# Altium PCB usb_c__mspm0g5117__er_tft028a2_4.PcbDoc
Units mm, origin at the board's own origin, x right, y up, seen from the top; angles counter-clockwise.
Board outline 82 x 52 mm, 2 copper layers (Top, Bottom), stack 0 mm thick; 33 components, 30 nets, 218 pads, 119 vias.
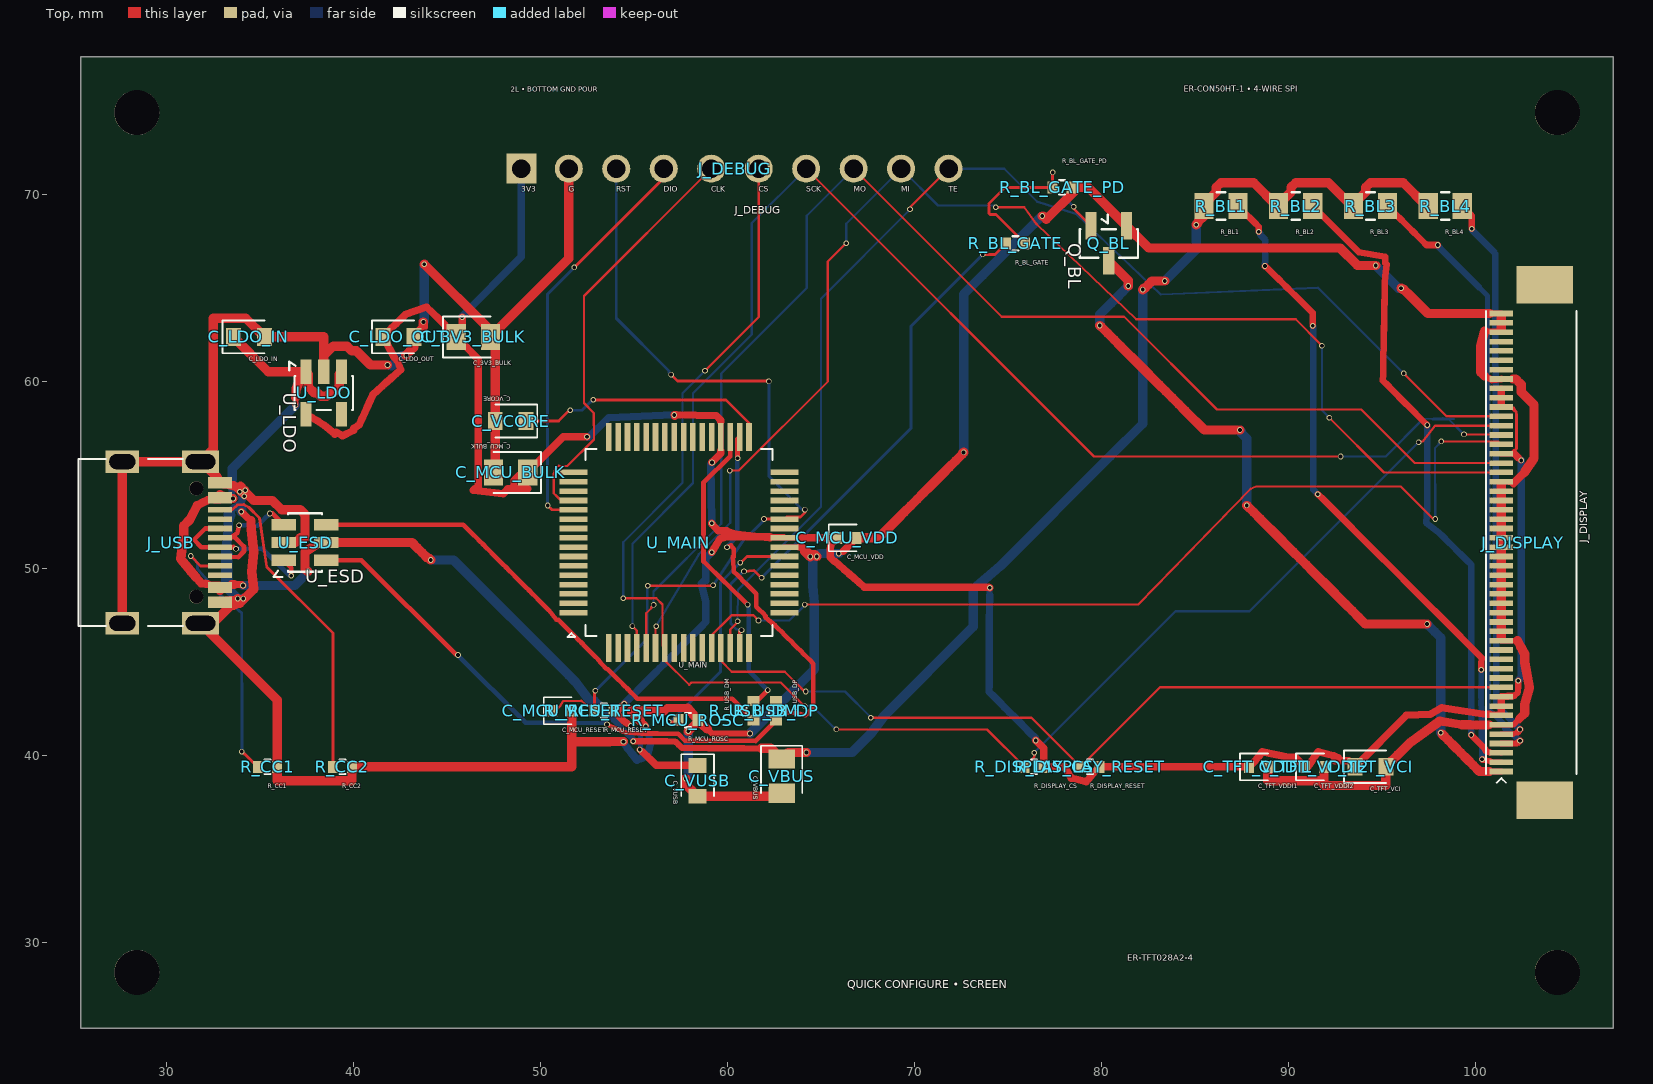
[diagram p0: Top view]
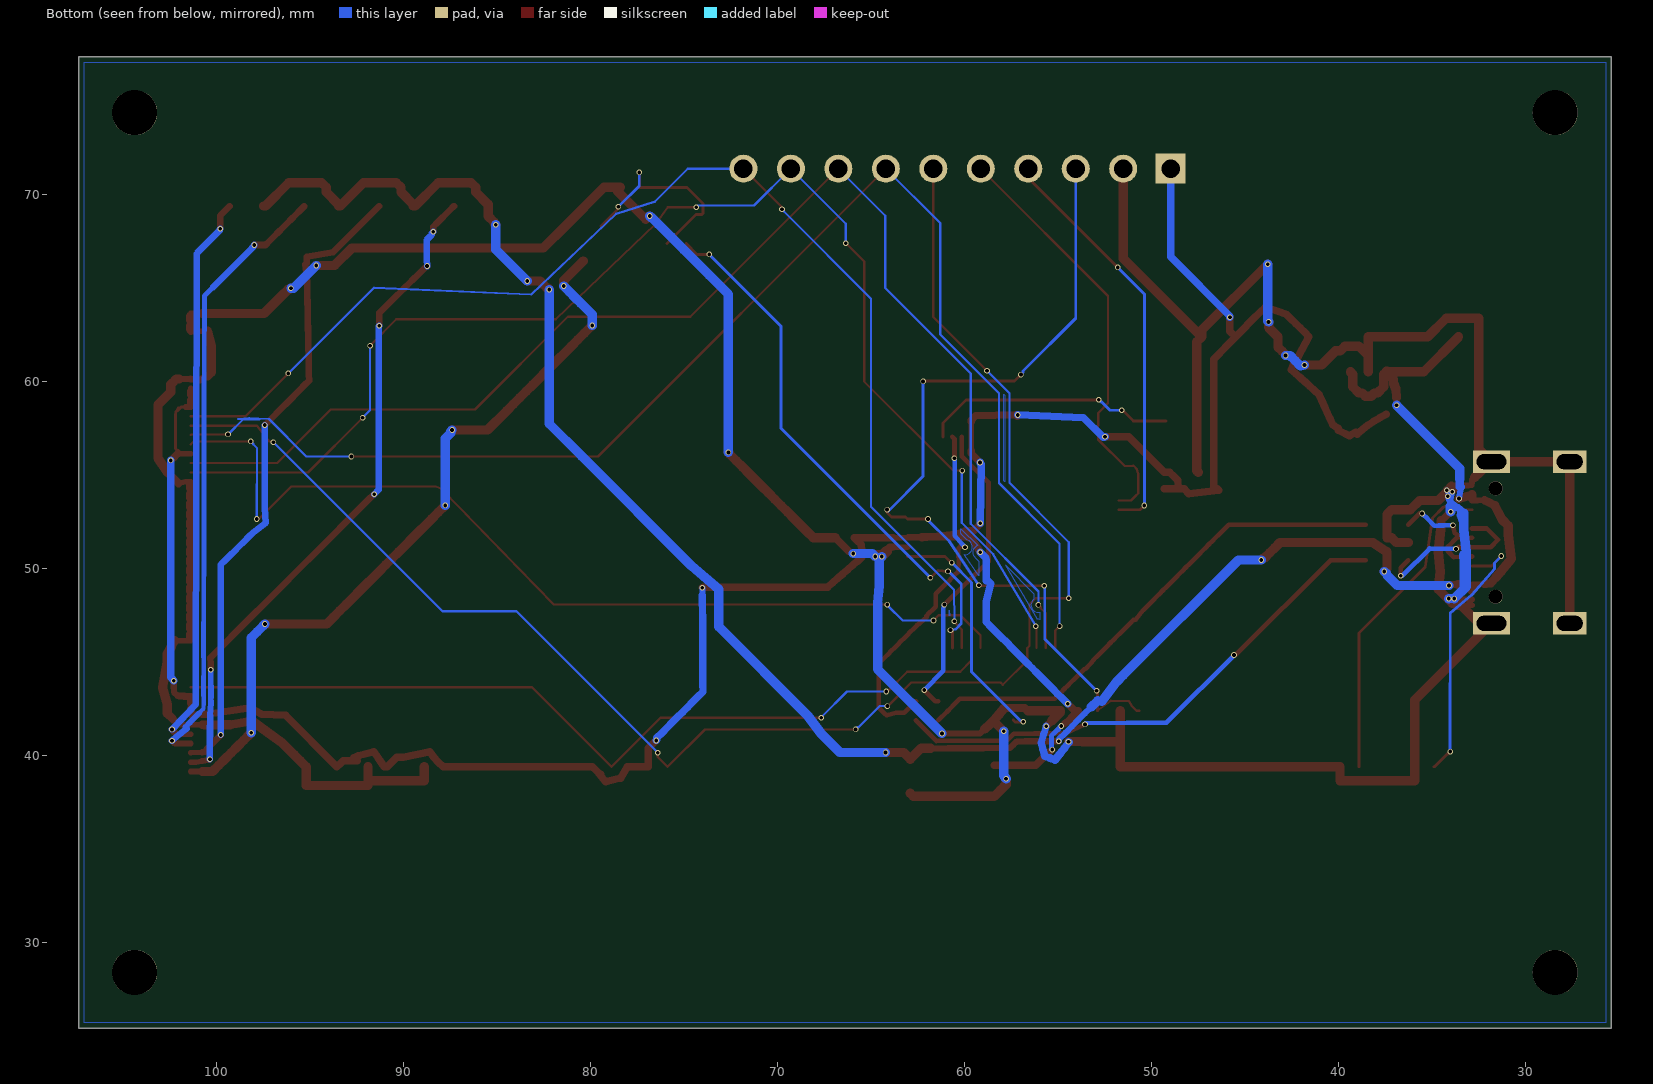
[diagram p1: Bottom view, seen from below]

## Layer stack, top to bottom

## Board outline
25.4,77.4 107.4,77.4 107.4,25.4 25.4,25.4

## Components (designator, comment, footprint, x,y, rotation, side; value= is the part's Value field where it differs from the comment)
C_3V3_BULK "" TSCIRCUIT-2.8500x1.4000mm 46.4,62.4 r0 top
C_LDO_IN "" TSCIRCUIT-2.4500x0.9500mm 34.4,62.4 r0 top
C_LDO_OUT "" TSCIRCUIT-2.4500x0.9500mm 42.4,62.4 r0 top
C_MCU_BULK "" TSCIRCUIT-2.8500x1.4000mm 48.4,55.15 r180 top
C_MCU_RESET "" TSCIRCUIT-1.5600x0.6400mm 51.15,42.4 r0 top
C_MCU_VDD "" TSCIRCUIT-1.5600x0.6400mm 66.4,51.65 r0 top
C_TFT_VCI "" TSCIRCUIT-2.4500x0.9500mm 94.4,39.4 r0 top
C_TFT_VDDI1 "" TSCIRCUIT-1.5600x0.6400mm 88.4,39.4 r0 top
C_TFT_VDDI2 "" TSCIRCUIT-1.5600x0.6400mm 91.4,39.4 r0 top
C_VBUS "" TSCIRCUIT-1.4000x2.8500mm 62.9,38.9 r270 top
C_VCORE "" TSCIRCUIT-2.4500x0.9500mm 48.4,57.9 r180 top
C_VUSB "" TSCIRCUIT-0.9500x2.4500mm 58.4,38.65 r270 top
J_DEBUG "" TSCIRCUIT-24.3600x1.5000mm 60.4,71.4 r0 top
J_DISPLAY "" TSCIRCUIT-4.4500x29.5800mm 103,51.4 r90 top
J_USB "" TSCIRCUIT-6.7732x9.8502mm 30.113,51.4 r90 top
Q_BL "" TSCIRCUIT-2.5000x3.3500mm 80.4,67.4 r270 top
R_BL1 "" TSCIRCUIT-2.8500x1.4000mm 86.4,69.4 r0 top
R_BL2 "" TSCIRCUIT-2.8500x1.4000mm 90.4,69.4 r0 top
R_BL3 "" TSCIRCUIT-2.8500x1.4000mm 94.4,69.4 r0 top
R_BL4 "" TSCIRCUIT-2.8500x1.4000mm 98.4,69.4 r0 top
R_BL_GATE "" TSCIRCUIT-1.5600x0.6400mm 75.4,67.4 r0 top
R_BL_GATE_PD "" TSCIRCUIT-1.5600x0.6400mm 77.9,70.4 r0 top
R_CC1 "" TSCIRCUIT-1.5600x0.6400mm 35.4,39.4 r0 top
R_CC2 "" TSCIRCUIT-1.5600x0.6400mm 39.4,39.4 r0 top
R_DISPLAY_CS "" TSCIRCUIT-1.5600x0.6400mm 76.4,39.4 r0 top
R_DISPLAY_RESET "" TSCIRCUIT-1.5600x0.6400mm 79.4,39.4 r0 top
R_MCU_RESET "" TSCIRCUIT-1.5600x0.6400mm 53.4,42.4 r0 top
R_MCU_ROSC "" TSCIRCUIT-1.5600x0.6400mm 57.9,41.9 r0 top
R_USB_DM "" TSCIRCUIT-0.6400x1.5600mm 61.4,42.4 r90 top
R_USB_DP "" TSCIRCUIT-0.6400x1.5600mm 62.6,42.4 r90 top
U_ESD "" TSCIRCUIT-3.6000x2.5000mm 37.4,51.4 r0 top
U_LDO "" TSCIRCUIT-2.5000x3.6000mm 38.4,59.4 r270 top
U_MAIN "" TSCIRCUIT-12.8000x12.8000mm 57.4,51.4 r0 top

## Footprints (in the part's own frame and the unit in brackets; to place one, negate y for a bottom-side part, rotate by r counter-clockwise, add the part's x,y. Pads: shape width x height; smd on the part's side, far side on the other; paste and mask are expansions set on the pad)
TSCIRCUIT-0.6400x1.5600mm [mm]
  rect 0.54x0.64 smd: 1(-0.51,0) 2(0.51,0)
  silkscreen extent -0.15,-0.38 0.15,0.38
TSCIRCUIT-0.9500x2.4500mm [mm]
  rect 0.8x0.95 smd: 1(-0.825,0) 2(0.825,0)
  silkscreen extent -1.43,-0.87 0.82,0.87
TSCIRCUIT-1.4000x2.8500mm [mm]
  rect 1.025x1.4 smd: 1(-0.913,0) 2(0.913,0)
  silkscreen extent -1.62,-1.1 0.91,1.1
TSCIRCUIT-1.5600x0.6400mm [mm]
  rect 0.54x0.64 smd: 1(-0.51,0) 2(0.51,0)
  silkscreen extent -0.98,-0.72 0.51,0.72
TSCIRCUIT-2.4500x0.9500mm [mm]
  rect 0.8x0.95 smd: 1(-0.825,0) 2(0.825,0)
  silkscreen extent -1.43,-0.87 0.82,0.87
TSCIRCUIT-2.5000x3.3500mm [mm]
  rect 1.475x0.6 smd: 1(-0.938,-0.95) 2(-0.938,0.95) 3(0.937,0)
  silkscreen extent -1.54,-1.56 0.76,1.56
TSCIRCUIT-2.5000x3.6000mm [mm]
  rect 1.325x0.6 smd: 1(-1.137,-0.95) 2(-1.137,0) 3(-1.137,0.95) 4(1.138,0.95) 5(1.138,-0.95)
  silkscreen extent -1.69,-1.84 0.91,1.56
TSCIRCUIT-2.8500x1.4000mm [mm]
  rect 1.025x1.4 smd: 1(-0.913,0) 2(0.913,0)
  silkscreen extent -1.63,-1.1 0.91,1.1
TSCIRCUIT-3.6000x2.5000mm [mm]
  rect 1.325x0.6 smd: 1(-1.137,-0.95) 2(-1.137,0) 3(-1.137,0.95) 4(1.138,0.95) 5(1.138,0) 6(1.138,-0.95)
  silkscreen extent -1.69,-1.84 0.91,1.56
TSCIRCUIT-4.4500x29.5800mm [mm]
  rect 0.3x1.25 smd: 1(-12.25,1.6) 2(-11.75,1.6) 3(-11.25,1.6) 4(-10.75,1.6) 5(-10.25,1.6) 6(-9.75,1.6) 7(-9.25,1.6) 8(-8.75,1.6) 9(-8.25,1.6) 10(-7.75,1.6) 11(-7.25,1.6) 12(-6.75,1.6) 13(-6.25,1.6) 14(-5.75,1.6) 15(-5.25,1.6) 16(-4.75,1.6) 17(-4.25,1.6) 18(-3.75,1.6) 19(-3.25,1.6) 20(-2.75,1.6) 21(-2.25,1.6) 22(-1.75,1.6) 23(-1.25,1.6) 24(-0.75,1.6) 25(-0.25,1.6) 26(0.25,1.6) 27(0.75,1.6) 28(1.25,1.6) 29(1.75,1.6) 30(2.25,1.6) 31(2.75,1.6) 32(3.25,1.6) 33(3.75,1.6) 34(4.25,1.6) 35(4.75,1.6) 36(5.25,1.6) 37(5.75,1.6) 38(6.25,1.6) 39(6.75,1.6) 40(7.25,1.6) 41(7.75,1.6) 42(8.25,1.6) 43(8.75,1.6) 44(9.25,1.6) 45(9.75,1.6) 46(10.25,1.6) 47(10.75,1.6) 48(11.25,1.6) 49(11.75,1.6) 50(12.25,1.6)
  rect 2x3 smd: 51(13.79,-0.725) 52(-13.79,-0.725)
  silkscreen extent -12.85,-2.43 12.4,2.42
TSCIRCUIT-6.7732x9.8502mm [mm]
  rect 0.3x1.3 smd: 1(-3.35,-2.737) 2(-3.05,-2.737) 3(-2.55,-2.737) 4(-2.25,-2.737) 5(-1.75,-2.737) 6(-1.25,-2.737) 7(-0.75,-2.737) 8(-0.25,-2.737) 9(0.25,-2.737) 10(0.75,-2.737) 11(1.25,-2.737) 12(1.75,-2.737) 13(2.55,-2.737) 14(2.25,-2.737) 15(3.35,-2.737) 16(3.05,-2.737)
  rect 1.2x2 hole 0.8 slot 1.6 at 90 deg: 17(-4.325,-1.693) 18(4.325,-1.693)
  rect 1.2x1.8 hole 0.8 slot 1.4 at 90 deg: 19(4.325,2.487) 20(-4.325,2.487)
  round 0.75 hole 0.75 unplated: NPTH-1(-2.9,-1.468) NPTH-2(2.9,-1.468)
  silkscreen extent -4.47,-0.75 4.47,4.83
TSCIRCUIT-12.8000x12.8000mm [mm]
  rect 1.5x0.3 smd: 1(-5.65,-3.75) 2(-5.65,-3.25) 3(-5.65,-2.75) 4(-5.65,-2.25) 5(-5.65,-1.75) 6(-5.65,-1.25) 7(-5.65,-0.75) 8(-5.65,-0.25) 9(-5.65,0.25) 10(-5.65,0.75) 11(-5.65,1.25) 12(-5.65,1.75) 13(-5.65,2.25) 14(-5.65,2.75) 15(-5.65,3.25) 16(-5.65,3.75) 33(5.65,3.75) 34(5.65,3.25) 35(5.65,2.75) 36(5.65,2.25) 37(5.65,1.75) 38(5.65,1.25) 39(5.65,0.75) 40(5.65,0.25) 41(5.65,-0.25) 42(5.65,-0.75) 43(5.65,-1.25) 44(5.65,-1.75) 45(5.65,-2.25) 46(5.65,-2.75) 47(5.65,-3.25) 48(5.65,-3.75)
  rect 0.3x1.5 smd: 17(-3.75,5.65) 18(-3.25,5.65) 19(-2.75,5.65) 20(-2.25,5.65) 21(-1.75,5.65) 22(-1.25,5.65) 23(-0.75,5.65) 24(-0.25,5.65) 25(0.25,5.65) 26(0.75,5.65) 27(1.25,5.65) 28(1.75,5.65) 29(2.25,5.65) 30(2.75,5.65) 31(3.25,5.65) 32(3.75,5.65) 49(3.75,-5.65) 50(3.25,-5.65) 51(2.75,-5.65) 52(2.25,-5.65) 53(1.75,-5.65) 54(1.25,-5.65) 55(0.75,-5.65) 56(0.25,-5.65) 57(-0.25,-5.65) 58(-0.75,-5.65) 59(-1.25,-5.65) 60(-1.75,-5.65) 61(-2.25,-5.65) 62(-2.75,-5.65) 63(-3.25,-5.65) 64(-3.75,-5.65)
  silkscreen extent -5.95,-5.05 5,5
TSCIRCUIT-24.3600x1.5000mm [mm]
  rect 1.6x1.6 hole 1: 1(-11.43,0)
  round 1.5 hole 1: 2(-8.89,0) 3(-6.35,0) 4(-3.81,0) 5(-1.27,0) 6(1.27,0) 7(3.81,0) 8(6.35,0) 9(8.89,0) 10(11.43,0)

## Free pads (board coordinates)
  round 2.4 hole 2.4 unplated: NPTH-3(28.4,28.4) NPTH-4(104.4,28.4) NPTH-5(28.4,74.4) NPTH-6(104.4,74.4)

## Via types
v1: diameter 0.3, hole 0.2, Top to Bottom, 119 vias

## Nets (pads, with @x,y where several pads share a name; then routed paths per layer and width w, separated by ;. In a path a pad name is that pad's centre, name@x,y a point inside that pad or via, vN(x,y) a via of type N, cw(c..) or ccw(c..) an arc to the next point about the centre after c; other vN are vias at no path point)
".J_DEBUG > .pin4 to .U_MAIN > .pin12": J_DEBUG.4 U_MAIN.12 | length 22.1
  Top w0.15: v1(50.378,53.378) 50.606,53.15 U_MAIN.12 ; v1(51.802,66.116) 51.815,66.129 56.59,70.904 J_DEBUG.4
  Bottom w0.15: v1(50.378,53.378) 50.37,53.386 50.37,53.404 50.37,64.684 v1(51.802,66.116)
".J_DEBUG > .pin5 to .U_MAIN > .pin13": J_DEBUG.5 U_MAIN.13 | length 22.8
  Top w0.12: U_MAIN.13 51.093,53.65 50.851,53.892 50.711,54.032 50.711,55.079 50.789,55.33 50.971,55.526 50.993,55.491 51.433,55.49 52.859,56.905 52.852,58.334 52.322,58.863 52.322,64.592 J_DEBUG.5
".U_MAIN > .pin42 to .R_MCU_ROSC > .pin1": R_MCU_ROSC.1 U_MAIN.42 | length 13.3
  Top w0.15: v1(56.86,41.804) 57.294,41.804 R_MCU_ROSC.1 ; v1(60.681,50.326) 60.673,50.3 60.695,50.3 61.046,50.65 U_MAIN.42
  Bottom w0.15: v1(56.86,41.804) 56.921,41.865 57.008,41.865 59.632,44.489 59.632,49.259 v1(60.681,50.326)
BACKLIGHT_ANODE_1: J_DISPLAY.2 R_BL1.2 | length 36.1
  Top w0.3: J_DISPLAY.2@100.785,39.709 101.122,39.65 J_DISPLAY.2
  Top w0.312: v1@100.449,39.767 J_DISPLAY.2@100.785,39.709
  Top w0.35: R_BL1.2 87.534,69.179 87.755,68.957 87.977,68.736 88.199,68.514 88.42,68.293 v1(88.42,68.021) ; v1(88.751,66.191) 88.784,66.181 89.014,65.953 89.245,65.726 89.475,65.499 89.705,65.271 89.935,65.044 90.165,64.816 90.396,64.589 90.626,64.362 90.856,64.134 91.086,63.907 91.316,63.679 91.317,63.339 v1(91.318,62.998) ; v1(91.583,53.984) 91.625,53.942 91.637,53.942 91.879,53.7 92.121,53.459 92.363,53.217 92.605,52.975 92.846,52.733 93.088,52.491 93.33,52.249 93.572,52.007 93.814,51.766 94.056,51.524 94.298,51.282 94.539,51.04 94.781,50.798 95.023,50.556 95.265,50.314 95.507,50.073 95.749,49.831 95.991,49.589 96.232,49.347 96.474,49.105 96.716,48.863 96.958,48.621 97.2,48.38 97.442,48.138 97.684,47.896 97.925,47.654 98.167,47.412 98.409,47.17 98.651,46.928 98.893,46.687 99.135,46.445 99.377,46.203 99.618,45.961 99.86,45.719 100.102,45.477 100.344,45.235 100.335,44.915 v1(100.325,44.594) ; v1(100.371,39.8) 100.433,39.767 v1@100.449,39.767
  Bottom w0.306: 100.319,43.12 100.317,42.825 100.34,42.484 100.363,42.143 ; 100.321,43.709 100.323,44.004 100.324,44.299 v1(100.325,44.594)
  Bottom w0.312: 100.319,43.12 100.32,43.415 100.321,43.709
  Bottom w0.35: v1(88.42,68.021) 88.508,67.933 88.508,67.853 88.644,67.718 88.779,67.582 88.772,67.234 88.765,66.886 88.758,66.539 v1(88.751,66.191) ; v1(91.318,62.998) 91.349,62.967 91.349,62.883 91.349,62.537 91.349,62.19 91.349,61.843 91.349,61.497 91.349,61.15 91.349,60.804 91.349,60.457 91.349,60.11 91.349,59.764 91.349,59.417 91.349,59.071 91.349,58.724 91.349,58.377 91.349,58.031 91.349,57.684 91.349,57.338 91.349,56.991 91.349,56.644 91.349,56.298 91.349,55.951 91.349,55.604 91.349,55.258 91.349,54.911 91.349,54.565 91.349,54.218 v1(91.583,53.984) ; 100.363,42.143 100.364,41.809 100.365,41.474 100.367,41.139 100.368,40.804 100.369,40.469 100.37,40.135 v1(100.371,39.8)
BACKLIGHT_ANODE_2: J_DISPLAY.3 R_BL2.2 | length 34.6
  Top w0.3: 100.775,40.19 J_DISPLAY.3
  Top w0.35: R_BL2.2 91.559,69.154 91.805,68.908 92.051,68.662 92.297,68.416 92.543,68.17 92.789,67.924 93.035,67.678 93.281,67.432 93.527,67.186 93.773,66.94 95.2,66.7 95.193,66.35 95.275,66.275 95.179,65.651 95.172,65.302 95.165,64.952 95.158,64.603 95.151,64.253 95.144,63.904 95.137,63.554 95.13,63.205 95.123,62.855 95.116,62.506 95.108,62.156 95.101,61.806 95.094,61.457 95.087,61.107 95.08,60.758 95.073,60.408 95.066,60.059 95.303,59.821 95.54,59.583 95.776,59.346 96.013,59.108 96.25,58.87 96.487,58.633 96.723,58.395 96.96,58.157 97.197,57.92 v1(97.433,57.682) ; v1(99.788,41.106) 99.794,41.1 100.031,40.863 100.269,40.625 100.506,40.388 100.612,40.2 100.775,40.19
  Bottom w0.35: v1(97.433,57.682) 97.435,57.63 97.435,57.292 97.435,56.955 97.435,56.618 97.435,56.281 97.435,55.943 97.435,55.606 97.435,55.269 97.435,54.932 97.435,54.595 97.435,54.257 97.435,53.92 97.435,53.583 97.435,53.246 97.375,52.45 98.052,51.932 98.3,51.687 98.548,51.442 98.796,51.197 99.044,50.953 99.292,50.708 99.54,50.463 99.788,50.218 99.788,49.88 99.788,49.543 99.788,49.205 99.788,48.868 99.788,48.531 99.788,48.193 99.788,47.856 99.788,47.518 99.788,47.181 99.788,46.843 99.788,46.506 99.788,46.168 99.788,45.831 99.788,45.493 99.788,45.156 99.788,44.818 99.788,44.481 99.788,44.143 99.788,43.806 99.788,43.468 99.788,43.131 99.788,42.793 99.788,42.456 99.788,42.118 99.788,41.781 99.788,41.443 v1(99.788,41.106)
BACKLIGHT_ANODE_3: J_DISPLAY.4 R_BL3.2 | length 33
  Top w0.3: J_DISPLAY.4 101.678,40.65 101.956,40.65 102.234,40.65
  Top w0.35: R_BL3.2 95.544,69.169 95.776,68.937 96.007,68.706 96.238,68.474 96.47,68.243 96.702,68.011 96.933,67.78 97.164,67.548 97.396,67.317 97.697,67.317 v1(97.998,67.317) ; 102.234,40.65 102.351,40.767 102.367,40.767 v1(102.4,40.8)
  Bottom w0.238: 100.711,43.203 100.711,42.858 100.712,42.514 100.953,42.269
  Bottom w0.25: 100.706,45.273 100.707,44.928 100.708,44.583 100.709,44.238
  Bottom w0.262: 100.188,65.069 100.428,64.828 100.667,64.587 100.668,64.242 100.669,63.897 100.669,63.552 100.67,63.207 100.671,62.862 100.672,62.518 100.672,62.173 100.673,61.828 100.674,61.483 100.674,61.138 100.675,60.793 100.676,60.448 100.676,60.103 100.677,59.758 100.678,59.413 100.679,59.069 100.679,58.724 100.68,58.379 100.681,58.034 100.681,57.689 100.682,57.344 100.683,56.999 100.683,56.654 100.684,56.309 100.685,55.965 100.685,55.62 100.686,55.275 100.687,54.93 100.688,54.585 100.688,54.24 100.689,53.895 100.69,53.55 100.69,53.205 100.691,52.86 100.692,52.516 100.692,52.171 100.693,51.826 100.694,51.481 100.695,51.136 100.695,50.791 100.696,50.446 100.697,50.101 100.697,49.756 100.698,49.411 100.699,49.067 100.699,48.722 100.7,48.377 100.701,48.032 100.702,47.687 100.702,47.342 100.703,46.997 100.704,46.652 100.704,46.307 100.705,45.963 100.706,45.618 100.706,45.273 ; 100.709,44.238 100.709,43.893 100.71,43.548 100.711,43.203
  Bottom w0.312: 100.953,42.269 101.194,42.024 101.435,41.779 101.677,41.534 101.619,41.447
  Bottom w0.35: v1(97.998,67.317) 98.032,67.283 98.032,67.238 98.271,66.997 98.511,66.756 98.751,66.515 98.99,66.274 99.23,66.033 99.469,65.792 99.709,65.551 99.949,65.31 100.188,65.069 ; 101.619,41.447 101.879,41.231 102.14,41.016 v1(102.4,40.8)
BACKLIGHT_ANODE_4: J_DISPLAY.5 R_BL4.2 | length 30.3
  Top w0.3: J_DISPLAY.5 101.494,41.15 101.588,41.15 101.681,41.15 101.775,41.15 101.869,41.15 101.963,41.15 102.025,41.15 102.275,41.25
  Top w0.35: R_BL4.2 99.82,68.893 v1(99.82,68.181) ; 102.275,41.25 v1(102.4,41.4)
  Bottom w0.35: v1(99.82,68.181) 99.851,68.15 99.851,68.091 101.055,66.887 101.071,66.841 101.119,42.748 v1(102.4,41.4)
BACKLIGHT_CATHODE: J_DISPLAY.1 Q_BL.3 | length 41
  Top w0.3: 100.775,39.15 100.837,39.15 100.931,39.15 101.025,39.15 101.119,39.15 101.213,39.15 101.306,39.15 J_DISPLAY.1
  Top w0.35: v1(98.155,41.219) 98.222,41.152 v1@98.229,41.152
  Top w0.475: 100.744,39.15 100.775,39.15
  Top w0.5: v1(79.922,63.012) 79.996,62.938 80.341,62.593 80.686,62.248 81.031,61.903 81.376,61.558 81.721,61.213 82.066,60.868 82.411,60.523 82.756,60.178 83.101,59.833 83.447,59.487 83.792,59.142 84.137,58.797 84.482,58.452 84.827,58.107 85.172,57.762 85.517,57.417 85.992,57.417 86.466,57.417 86.941,57.417 v1(87.416,57.417) ; Q_BL.3 81.445,65.417 v1(81.445,65.123) ; v1(87.783,53.383) 87.8,53.366 88.152,53.014 88.503,52.663 88.854,52.312 89.205,51.961 89.557,51.609 89.908,51.258 90.259,50.907 90.61,50.556 90.962,50.204 91.313,49.853 91.664,49.502 92.015,49.151 92.367,48.799 92.718,48.448 93.069,48.097 93.42,47.746 93.772,47.394 94.123,47.043 94.595,47.043 95.067,47.043 95.539,47.043 96.011,47.043 96.483,47.043 96.955,47.043 v1(97.427,47.043) ; v1@98.229,41.152 98.563,40.819 98.897,40.485 99.231,40.151 99.564,39.817 99.898,39.484 100.232,39.15 100.65,39.15 100.744,39.15
  Bottom w0.5: v1(79.922,63.012) 79.922,63.306 79.922,63.6 80.226,63.904 80.531,64.209 80.835,64.513 81.139,64.817 81.443,65.121 v1(81.445,65.123) ; v1(87.416,57.417) 87.49,57.343 87.49,57.259 87.783,56.966 87.783,56.518 87.783,56.07 87.783,55.622 87.783,55.174 87.783,54.727 87.783,54.279 87.783,53.831 v1(87.783,53.383) ; v1(97.427,47.043) 97.511,46.959 97.511,46.95 97.833,46.628 98.155,46.306 98.155,45.844 98.155,45.381 98.155,44.919 98.155,44.456 98.155,43.994 98.155,43.531 98.155,43.069 98.155,42.606 98.155,42.144 98.155,41.681 v1(98.155,41.219)
BACKLIGHT_GATE: Q_BL.1 R_BL_GATE.2 R_BL_GATE_PD.1 | length 11.4
  Top w0.15: R_BL_GATE.2 74.366,68.944 74.05,68.944 73.996,68.997 73.996,69.544 74.852,70.4 R_BL_GATE_PD.1 77.39,71.139 77.398,71.147 v1(77.4,71.2) v1(77.4,71.2) ; v1(78.515,69.356) 78.515,69.272 Q_BL.1
  Bottom w0.15: v1(77.4,71.2) 77.4,70.475 78.478,69.397 78.478,69.393 v1(78.515,69.356)
BACKLIGHT_PWM: R_BL_GATE.1 U_MAIN.50 | length 29.6
  Top w0.15: U_MAIN.50 60.65,46.624 60.739,46.713 60.739,46.729 v1(60.748,46.716) ; v1(60.883,49.853) 61.422,49.897 61.73,49.589 61.751,49.589 v1(61.824,49.516) ; v1(73.662,66.812) 74.302,66.812 R_BL_GATE.1
  Bottom w0.15: v1(60.748,46.716) 60.488,46.755 60.172,47.071 60.172,49.189 60.795,49.812 60.795,49.832 v1(60.883,49.853) ; v1(61.824,49.516) 69.819,57.511 69.819,62.982 69.832,62.982 73.648,66.798 v1(73.662,66.812)
DISPLAY_CS_N: J_DEBUG.6 J_DISPLAY.38 R_DISPLAY_CS.1 U_MAIN.58 | length 86.2
  Top w0.12: v1(54.417,48.416) 56.193,48.416 56.526,48.083 56.526,45.874 U_MAIN.58 56.65,45.093 57.953,43.79 58.069,43.906 62.784,43.906 62.844,43.906 64.039,42.712 64.064,42.712 v1(64.126,42.65) ; v1(58.799,60.592) 58.973,60.766 61.67,63.464 J_DEBUG.6 ; v1(65.826,41.4) 73.89,41.4 R_DISPLAY_CS.1 76.41,39.92 v1(76.41,40.152) ; v1(96.974,56.765) 97.005,56.796 97.18,56.8 97.86,57.649 J_DISPLAY.38
  Bottom w0.12: v1(54.417,48.416) 54.423,48.422 54.423,48.657 54.423,51.417 57.597,54.591 57.597,59.39 v1(58.799,60.592) ; v1(64.126,42.65) 64.537,42.65 65.659,41.527 65.699,41.527 v1(65.826,41.4) ; v1(76.41,40.152) 76.43,40.172 83.973,47.715 83.973,47.72 87.929,47.72 v1(96.974,56.765)
DISPLAY_DC: J_DISPLAY.36 U_MAIN.53 | length 51.3
  Top w0.12: U_MAIN.53 59.15,46.436 60.079,47.365 60.22,47.513 61.271,47.509 61.386,47.506 v1(61.662,47.23) ; v1(64.137,48.079) 81.971,48.079 88,54.28 88.292,54.4 96.014,54.4 97.8,52.614 97.814,52.614 v1(97.859,52.659) ; v1(98.18,56.809) 101.241,56.809 J_DISPLAY.36
  Bottom w0.12: v1(61.662,47.23) 63.31,47.23 64.088,48.009 64.093,48.009 v1(64.137,48.079) ; v1(97.859,52.659) 97.845,56.445 98.058,56.658 98.058,56.687 v1(98.18,56.809)
DISPLAY_MISO: J_DEBUG.9 J_DISPLAY.33 U_MAIN.59 | length 71.9
  Top w0.12: U_MAIN.59 56.15,46.747 56.152,46.749 56.152,46.885 v1(56.182,46.915) ; v1(60.124,55.247) 60.6,55.247 65.36,60.007 65.36,66.428 66.296,67.364 v1(66.349,67.417) ; v1(74.354,69.332) 75.876,69.332 76.542,68.432 81.869,63.338 90.396,63.338 v1@91.753,61.981 ; v1@91.753,61.98 v1(91.801,61.932) ; v1(92.201,58.075) 95.126,55.15 J_DISPLAY.33
  Bottom w0.12: v1(56.182,46.915) 58.463,50.777 60.144,52.458 60.144,55.079 60.144,55.227 v1(60.124,55.247) ; v1(66.349,67.417) 66.349,68.459 J_DEBUG.9 71.258,69.432 74.225,69.432 74.254,69.432 v1(74.354,69.332) ; v1(91.801,61.932) 91.801,58.475 92.181,58.095 v1(92.201,58.075)
DISPLAY_MOSI: J_DEBUG.8 J_DISPLAY.34 U_MAIN.60 | length 71.4
  Top w0.12: U_MAIN.60 55.65,47.617 55.921,47.888 55.921,47.944 v1(56.046,48.062) ; J_DEBUG.8 74.667,63.483 81.219,63.483 86.193,58.51 93.908,58.51 96.768,55.65 J_DISPLAY.34
  Bottom w0.12: v1(56.046,48.062) 56.039,48.775 59.67,52.406 59.67,60.447 64.235,65.012 64.235,68.885 J_DEBUG.8
DISPLAY_RESET_N: J_DISPLAY.10 R_DISPLAY_RESET.1 U_MAIN.52 | length 46.6
  Top w0.12: U_MAIN.52 59.65,45.075 60.233,44.492 63.06,44.492 64.066,43.486 64.136,43.486 v1(64.191,43.431) ; v1(67.662,42.023) 76.266,42.024 R_DISPLAY_RESET.1 83.14,43.65 J_DISPLAY.10
  Bottom w0.12: v1(64.191,43.431) 66.283,43.431 67.631,42.083 67.648,42.083 v1(67.662,42.023)
DISPLAY_SCLK: J_DEBUG.7 J_DISPLAY.37 U_MAIN.61 | length 76.7
  Top w0.12: v1(54.915,46.929) 54.934,46.91 55.15,46.694 U_MAIN.61 ; J_DEBUG.7 79.61,56 92.581,56 v1(92.8,56) ; v1(99.404,57.182) 101.368,57.182 J_DISPLAY.37
  Bottom w0.12: v1(54.915,46.929) 54.915,51.341 58.159,54.584 58.159,59.388 61.3,62.53 61.3,68.49 J_DEBUG.7 ; v1(92.8,56) 95.214,56 97.214,58.008 98.26,58.06 98.875,58.001 97.714,58 98.586,58 99.38,57.206 v1(99.404,57.182)
DISPLAY_TE: J_DEBUG.10 J_DISPLAY.39 U_MAIN.51 | length 65.5
  Top w0.12: U_MAIN.51 60.15,46.744 60.508,47.102 60.508,47.106 v1(60.539,47.186) ; v1(69.764,69.225) 69.764,69.334 J_DEBUG.10 ; v1(96.181,60.448) 96.299,60.33 96.299,60.318 98.467,58.15 J_DISPLAY.39
  Bottom w0.12: v1(60.539,47.186) 60.559,48.877 64.998,53.316 64.998,64.447 69.676,69.125 69.676,69.137 v1(69.764,69.225) ; J_DEBUG.10 74.807,71.4 76.578,69.629 78.631,68.985 83.181,64.671 91.596,65.033 v1(96.181,60.448)
GND: C_3V3_BULK.2 C_LDO_IN.2 C_LDO_OUT.2 C_MCU_BULK.2 C_MCU_RESET.2 C_MCU_VDD.2 C_TFT_VCI.2 C_TFT_VDDI1.2 C_TFT_VDDI2.2 C_VBUS.2 C_VCORE.2 C_VUSB.2 J_DEBUG.2 J_DISPLAY.6 J_DISPLAY.15 J_DISPLAY.16 J_DISPLAY.17 J_DISPLAY.18 J_DISPLAY.19 J_DISPLAY.20 J_DISPLAY.21 J_DISPLAY.22 J_DISPLAY.23 J_DISPLAY.24 J_DISPLAY.25 J_DISPLAY.26 J_DISPLAY.27 J_DISPLAY.28 J_DISPLAY.29 J_DISPLAY.30 J_DISPLAY.31 J_DISPLAY.32 J_DISPLAY.43 J_DISPLAY.48 J_DISPLAY.49 J_DISPLAY.50 J_USB.1 J_USB.2 J_USB.15 J_USB.16 J_USB.17 J_USB.18 J_USB.19 J_USB.20 Q_BL.2 R_BL_GATE_PD.2 R_CC1.2 R_CC2.2 R_MCU_ROSC.2 U_ESD.2 U_LDO.2 U_MAIN.41 | length 269.2
  Top w0.275: J_USB.16 J_USB.16@33.16,54.45
  Top w0.288: J_USB.15@32.849,54.6 J_USB.16 ; J_USB.16 J_USB.16@32.945,54.461 ; J_USB.16 J_USB.16@32.945,54.461 ; J_USB.16 J_USB.16@32.945,54.461 ; J_USB.16@32.945,54.461 33.037,54.45 J_USB.16@32.945,54.461
  Top w0.3: 32.699,54.9 J_USB.15 J_USB.16@32.849,54.6 ; J_USB.1 32.943,48.05 33.037,48.05 33.13,48.05 33.224,48.05 33.318,48.05 33.412,48.05 33.499,48.05 ; J_USB.2 J_USB.2@32.906,48.333 ; J_USB.16@32.945,54.461 J_USB.16@33.037,54.45 ; 33.505,54.45 33.499,54.45 ; 33.95,54.45 J_USB.16@33.224,54.45 ; 100.5,62.7 100.8,62.7 101.1,62.7 J_DISPLAY.48 101.4,62.8 ; 100.775,41.65 100.837,41.65 100.931,41.65 101.025,41.65 101.119,41.65 101.213,41.65 101.306,41.65 J_DISPLAY.6 101.722,41.65 102.025,41.65 102.044,41.65 102.348,41.953 ; 100.775,63.65 100.837,63.65 100.931,63.65 101.025,63.65 101.119,63.65 101.213,63.65 101.306,63.65 J_DISPLAY.50 J_DISPLAY.50@101.4,63.5 ; J_DISPLAY.15@101.4,46.3 J_DISPLAY.15 101.672,46.15 101.974,46.15 102.275,46.15 ; J_DISPLAY.16@101.4,46.5 J_DISPLAY.16 J_DISPLAY.16@101.4,46.8 ; J_DISPLAY.17@101.4,47 J_DISPLAY.17 101.4,47.3 ; J_DISPLAY.18@101.4,47.5 J_DISPLAY.18 J_DISPLAY.18@101.4,47.8 ; J_DISPLAY.19@101.4,48 J_DISPLAY.19 101.4,48.3 ; J_DISPLAY.20@101.4,48.5 J_DISPLAY.20 101.4,48.8 ; J_DISPLAY.21@101.4,49 J_DISPLAY.21 J_DISPLAY.21@101.4,49.3 ; J_DISPLAY.22@101.4,49.5 J_DISPLAY.22 J_DISPLAY.22@101.4,49.8 ; J_DISPLAY.23@101.4,50 J_DISPLAY.23 101.4,50.3 ; J_DISPLAY.24@101.4,50.5 J_DISPLAY.24 101.4,50.8 ; J_DISPLAY.25@101.4,51 J_DISPLAY.25 J_DISPLAY.25@101.4,51.3 ; J_DISPLAY.26@101.4,51.5 J_DISPLAY.26 J_DISPLAY.26@101.4,51.8 ; 101.4,52 J_DISPLAY.27 101.4,52.3 ; J_DISPLAY.28@101.4,52.5 J_DISPLAY.28 101.4,52.8 ; J_DISPLAY.29@101.4,53 J_DISPLAY.29 101.4,53.3 ; J_DISPLAY.30@101.4,53.5 J_DISPLAY.30 101.4,53.8 ; J_DISPLAY.31@101.4,54 J_DISPLAY.31 J_DISPLAY.31@101.4,54.3 ; J_DISPLAY.32@101.4,54.5 J_DISPLAY.32 101.667,54.65 102.056,54.572 ; J_DISPLAY.43 101.712,60.15 102.025,60.15 ; J_DISPLAY.49@101.4,63 J_DISPLAY.49 J_DISPLAY.49@101.4,63.3 ; J_USB.16@33.037,54.45 J_USB.16@33.13,54.45 ; J_USB.16@33.037,54.45 J_USB.16@33.13,54.45 ; J_USB.16@33.037,54.45 J_USB.16@33.13,54.45 ; J_USB.16@33.13,54.45 J_USB.16@33.224,54.45 ; J_USB.16@33.13,54.45 J_USB.16@33.224,54.45 ; J_USB.16@33.13,54.45 J_USB.16@33.224,54.45 ; J_USB.16@33.224,54.45 J_USB.16@33.318,54.45 ; J_USB.16@33.224,54.45 J_USB.16@33.318,54.45 ; J_USB.16@33.318,54.45 J_USB.16@33.412,54.45 ; J_USB.16@33.318,54.45 J_USB.16@33.412,54.45 ; J_USB.16@33.412,54.45 33.499,54.45 ; J_USB.16@33.412,54.45 33.499,54.45 ; U_MAIN.41@63.144,51.15 U_MAIN.41 U_MAIN.41@63.144,51.15 ; U_MAIN.41@63.144,51.15 U_MAIN.41@63.238,51.15 ; U_MAIN.41@63.144,51.15 U_MAIN.41@63.238,51.15 ; U_MAIN.41@63.238,51.15 U_MAIN.41@63.331,51.15 ; U_MAIN.41@63.238,51.15 U_MAIN.41@63.331,51.15 ; U_MAIN.41@63.331,51.15 U_MAIN.41@63.425,51.15 ; U_MAIN.41@63.331,51.15 U_MAIN.41@63.425,51.15 ; U_MAIN.41@63.425,51.15 U_MAIN.41@63.519,51.15 ; U_MAIN.41@63.425,51.15 U_MAIN.41@63.519,51.15 ; U_MAIN.41@63.519,51.15 U_MAIN.41@63.612,51.15 ; U_MAIN.41@63.519,51.15 U_MAIN.41@63.612,51.15 ; U_MAIN.41@63.612,51.15 U_MAIN.41@63.706,51.15 ; U_MAIN.41@63.612,51.15 U_MAIN.41@63.706,51.15 ; U_MAIN.41@63.706,51.15 63.8,51.15 U_MAIN.41@63.706,51.15
  Top w0.31: v1(65.952,50.808) 66.182,50.922
  Top w0.312: J_USB.16@33.16,54.45 33.467,54.363 33.744,54.369
  Top w0.325: J_USB.2@32.906,48.333 33.353,48.367 v1(34.1,48.4) ; v1@55.586,41.615 v1(55.628,41.573) ; 58.911,41.424 59.162,41.186 59.571,41.185 59.98,41.184 60.389,41.183 60.797,41.182 v1(61.206,41.181)
  Top w0.35: 33.572,54.45 33.591,54.431 ; v1(33.906,54.116) v1@33.893,54.129 ; v1(34.15,53.875) v1@33.893,54.129 ; 33.591,54.431 v1@33.893,54.129 ; 33.591,54.431 v1@33.893,54.129
  Top w0.375: v1(33.993,53.051) 34.252,52.804 34.512,52.557 ; 64.133,50.922 63.906,51.15 63.8,51.15 64.001,51.15 64.195,50.956 ; 100.5,60.3 100.9,60.1 101.15,60.125 J_DISPLAY.43
  Top w0.4: 55.342,41.852 55.579,41.615 v1@55.586,41.615 ; 66.182,50.922 66.425,51.165 66.667,51.407 C_MCU_VDD.2
  Top w0.425: 33.95,54.45 v1(34.2,54.2)
  Top w0.437: 56.606,42.4 56.775,42.541 57.14,42.541 57.504,42.541 57.869,42.541 ; 102.056,54.572 102.348,54.864 102.64,55.155
  Top w0.45: 102.348,41.953 102.651,42.256
  Top w0.475: 33.499,54.45 33.505,54.45 ; 33.591,54.431 33.572,54.45 ; 53.688,40.747 54.063,40.747 v1(54.438,40.747) ; 98.119,41.848 99.289,41.65 ; 100.207,41.64 100.671,41.629 100.744,41.65 100.775,41.65 ; 100.3,60.5 100.5,60.3 ; 102.025,60.15 102.166,60.15 102.384,59.931 ; 102.275,46.15 102.448,45.812 ; 33.505,54.45 33.572,54.45 ; 33.505,54.45 33.572,54.45
  Top w0.5: J_USB.20 J_USB.19 J_USB.18 ; 32.699,54.9 32.474,55.125 31.874,55.725 J_USB.18 ; 33.499,48.05 33.505,48.05 33.586,48.05 33.597,48.057 33.9,48.15 34.65,48.9 34.541,49.837 34.65,50.9 34.517,52.104 34.512,52.557 ; 33.744,54.369 33.963,54.236 34.064,54.236 34.65,53.65 35.65,53.65 36.15,53.15 37.15,53.15 37.4,52.9 37.4,51.65 37.15,51.65 36.9,51.4 U_ESD.2 ; v1(33.8,48.4) 32.475,47.075 J_USB.17 35.91,42.971 R_CC1.2 35.91,38.65 39.91,38.65 R_CC2.2 40.396,39.4 40.882,39.4 41.368,39.4 41.854,39.4 42.341,39.4 42.827,39.4 43.313,39.4 43.799,39.4 44.285,39.4 44.771,39.4 45.257,39.4 45.743,39.4 46.229,39.4 46.716,39.4 51.66,39.4 C_MCU_RESET.2 51.66,40.747 53.688,40.747 ; v1(41.811,60.896) 41.807,60.9 40.9,60.9 40.15,61.65 39.9,61.65 39.65,61.9 38.9,61.9 38.4,61.4 U_LDO.2 38.4,62.4 C_LDO_IN.2 34.225,63.4 32.484,63.4 32.484,56.409 32.484,56.404 J_USB.18 ; v1(42.824,61.403) 42.787,61.413 43.006,61.633 43.225,61.852 43.225,62.126 C_LDO_OUT.2 43.732,62.907 v1(43.732,63.2) ; v1(43.783,66.292) 47.313,62.763 C_3V3_BULK.2 ; C_MCU_BULK.2 47.575,55.237 C_VCORE.2 47.575,62.138 C_3V3_BULK.2 ; J_DEBUG.2 51.51,66.597 C_3V3_BULK.2 ; 55.342,41.852 55.105,42.09 54.868,42.327 54.868,42.4 55.302,42.4 55.737,42.4 56.172,42.4 56.606,42.4 ; v1(57.775,38.755) 57.775,38.45 58.087,38.138 C_VUSB.2 62.737,37.825 C_VBUS.2 ; 57.869,42.541 58.139,42.22 R_MCU_ROSC.2 ; v1(57.9,41.3) 58.41,41.81 R_MCU_ROSC.2 ; 58.911,41.424 58.661,41.662 58.648,41.662 R_MCU_ROSC.2 ; 64.133,50.922 64.361,50.694 64.381,50.694 v1(64.428,50.647) ; 64.195,50.956 64.389,50.762 64.663,50.762 v1(64.775,50.65) ; C_MCU_VDD.2 67.301,51.65 67.693,51.65 68.084,51.65 68.428,51.994 68.772,52.338 69.116,52.682 69.46,53.026 69.804,53.37 70.149,53.715 70.493,54.059 70.837,54.403 71.181,54.747 71.525,55.091 71.869,55.435 72.213,55.779 72.557,56.123 72.557,56.145 v1(72.632,56.22) ; v1(76.846,68.866) 76.876,68.866 77.053,68.689 78.587,70.223 R_BL_GATE_PD.2 79.287,70.4 Q_BL.2 82.533,67.154 84.466,67.154 92.774,67.154 93.701,66.227 94.191,66.224 v1(94.681,66.22) ; C_TFT_VDDI1.2 88.91,38.65 91.91,38.65 C_TFT_VDDI2.2 91.91,38.4 95.225,38.4 C_TFT_VCI.2 95.546,39.721 95.868,40.043 96.189,40.364 96.511,40.686 98.119,41.848 ; v1(96.036,65.005) 96.1,64.941 96.185,64.941 96.508,64.618 96.831,64.296 97.153,63.973 97.476,63.65 97.93,63.65 98.383,63.65 98.836,63.65 99.29,63.65 99.743,63.65 100.197,63.65 100.65,63.65 100.744,63.65 100.775,63.65 ; 99.289,41.65 99.743,41.65 100.207,41.64 ; 100.3,60.5 100.3,60.967 100.3,61.433 100.3,61.9 100.5,62.7 ; 101.4,46.3 101.4,46.5 ; 101.4,46.8 J_DISPLAY.17@101.4,47 ; 101.4,47.3 101.4,47.5 ; J_DISPLAY.18@101.4,47.8 101.4,48 ; 101.4,48.3 J_DISPLAY.20@101.4,48.5 ; 101.4,48.8 101.4,49 ; 101.4,49.3 J_DISPLAY.22@101.4,49.5 ; 101.4,49.8 J_DISPLAY.23@101.4,50 ; 101.4,50.3 101.4,50.5 ; 101.4,50.8 J_DISPLAY.25@101.4,51 ; 101.4,51.3 101.4,51.5 ; 101.4,51.8 101.4,52 ; 101.4,52.3 101.4,52.5 ; 101.4,52.8 101.4,53 ; 101.4,53.3 J_DISPLAY.30@101.4,53.5 ; 101.4,53.8 101.4,54 ; 101.4,54.3 J_DISPLAY.32@101.4,54.5 ; 101.4,62.8 101.4,63 ; 101.4,63.3 J_DISPLAY.50@101.4,63.5 ; 102.384,59.931 102.466,59.849 102.466,59.453 103.15,58.769 103.15,55.9 102.64,55.155 ; 102.448,45.812 102.62,45.475 102.651,45.444 102.651,44.989 102.9,43.65 102.651,42.712 102.651,42.256
  Bottom w0.312: 33.425,52.864 33.553,53.197 33.805,53.419 34.057,53.641 v1(34.15,53.875) ; 33.664,53.299 34.04,53.621 33.973,53.868 v1(33.906,54.116) ; 34.02,53.583 33.963,53.849 v1(34.2,54.2)
  Bottom w0.325: 34.02,53.331 34.02,53.583
  Bottom w0.375: v1@54.4,40.712 v1(54.438,40.747) ; v1(55.628,41.573) 55.764,41.143 55.9,40.712 55.806,40.338
  Bottom w0.4: 33.287,52.977 33.664,53.299 ; v1@54.4,40.712 54.65,40.4 ; 55.431,39.869 55.712,39.963 55.806,40.338
  Bottom w0.425: 54.65,40.4 54.9,40.087 55.15,39.775 55.431,39.869
  Bottom w0.475: v1@34.02,53.078 34.02,53.331
  Bottom w0.5: 33.287,52.977 33.287,52.516 33.287,52.056 33.15,50.9 ; 33.425,52.864 33.298,52.53 33.295,52.085 33.15,50.9 ; v1(33.8,48.4) 33.15,49.05 33.15,50.9 ; v1(33.993,53.051) v1@34.02,53.078 ; v1(34.1,48.4) 33.783,48.417 33.548,48.652 33.312,48.888 33.272,48.97 33.275,49.415 33.279,49.86 33.282,50.305 33.285,50.75 33.15,50.9 ; v1(41.811,60.896) 42.01,60.849 42.029,60.849 42.305,61.124 42.581,61.4 v1(42.824,61.403) ; v1(43.732,63.2) 43.783,63.251 v1(43.783,66.292) ; v1(57.775,38.755) 57.818,38.798 57.818,38.835 57.9,38.917 57.9,39.394 57.9,39.87 57.9,40.347 57.9,40.823 v1(57.9,41.3) ; v1(61.206,41.181) 64.65,44.625 64.65,48.15 64.558,49.073 64.558,49.559 64.559,50.045 64.559,50.531 v1(64.428,50.647) ; v1(64.775,50.65) 64.933,50.808 v1(65.952,50.808) ; v1(72.632,56.22) 72.632,56.718 72.632,57.216 72.632,57.714 72.632,58.212 72.632,58.71 72.632,59.208 72.632,59.706 72.632,60.204 72.632,60.702 72.632,61.2 72.632,61.697 72.632,62.195 72.632,62.693 72.632,63.191 72.632,63.689 72.632,64.187 72.632,64.685 72.973,65.026 73.313,65.367 73.654,65.707 73.995,66.048 74.336,66.389 74.676,66.73 75.017,67.07 75.358,67.411 75.698,67.752 76.039,68.092 76.38,68.433 76.721,68.774 76.754,68.774 v1(76.846,68.866) ; v1(94.681,66.22) 95.896,65.005 v1(96.036,65.005)
MAIN_RESET: C_MCU_RESET.1 J_DEBUG.3 R_MCU_RESET.1 U_MAIN.38 | length 46.4
  Top w0.12: C_MCU_RESET.1 50.798,42.4 51.04,42.642 51.2,42.91 52.18,42.94 52.215,42.91 R_MCU_RESET.1
  Top w0.15: R_MCU_RESET.1 52.89,43.397 52.888,43.399 52.888,43.415 v1(52.936,43.471) ; v1(55.733,49.085) 58.982,49.085 59.154,49.085 v1(59.231,49.117) ; v1(56.983,60.384) 57.331,60.036 62.088,60.036 62.197,60.036 v1(62.216,60.017) ; v1(61.955,52.656) 63.044,52.656 U_MAIN.38 63.166,52.766 63.897,52.766 64.143,53.012 v1(64.143,53.161)
  Bottom w0.15: v1(52.936,43.471) 55.707,46.245 55.705,48.997 55.71,49.062 v1(55.733,49.085) ; J_DEBUG.3 54.05,63.4 56.879,60.572 56.879,60.488 v1(56.983,60.384) ; v1(59.231,49.117) 60.85,51.5 61.891,52.541 61.891,52.592 v1(61.955,52.656) ; v1(62.216,60.017) 62.216,54.948 64.073,53.091 v1(64.143,53.161)
MSP_VCORE: C_VCORE.1 U_MAIN.32 | length 13.7
  Top w0.15: C_VCORE.1 50.968,57.9 51.503,58.435 51.554,58.435 v1(51.592,58.473) ; v1(52.821,59.031) 59.915,59.031 61.149,57.797 U_MAIN.32
  Bottom w0.15: v1(51.592,58.473) 52.221,58.473 52.659,58.912 52.702,58.912 v1(52.821,59.031)
usb-dm-mcu: R_USB_DM.2 U_MAIN.30 | length 16.6
  Top w0.25: U_MAIN.30 60.15,56.003 58.721,54.621 58.716,50.387 v1(61.075,48.08) ; R_USB_DM.2 61.562,42.91 62.154,43.502 v1(62.156,43.504)
  Bottom w0.25: v1(61.075,48.08) 61.118,48.037 61.142,47.822 61.13,44.541 v1(62.156,43.504)
usb-dm-phy: R_USB_DM.1 U_ESD.4 | length 27.2
  Top w0.25: U_ESD.4 38.782,52.35 39.026,52.35 39.271,52.35 39.515,52.35 39.759,52.35 40.004,52.35 40.248,52.35 40.493,52.35 40.737,52.35 40.981,52.35 41.226,52.35 41.47,52.35 41.715,52.35 41.959,52.35 42.203,52.35 42.448,52.35 42.692,52.35 42.936,52.35 43.181,52.35 43.425,52.35 43.67,52.35 43.914,52.35 44.158,52.35 44.403,52.35 44.647,52.35 44.892,52.35 45.136,52.35 45.38,52.35 45.625,52.35 45.869,52.35 46.045,52.174 46.22,51.999 46.396,51.823 46.572,51.647 46.747,51.472 46.923,51.296 47.099,51.12 47.275,50.945 47.45,50.769 47.626,50.593 47.802,50.417 47.977,50.242 48.153,50.066 48.329,49.89 48.504,49.715 48.68,49.539 48.856,49.363 49.031,49.188 49.207,49.012 49.383,48.836 49.558,48.661 49.734,48.485 49.91,48.309 50.086,48.134 50.261,47.958 50.437,47.782 50.838,47.275 50.964,47.255 51.14,47.079 51.315,46.904 51.491,46.728 51.667,46.552 51.842,46.377 52.018,46.201 52.194,46.025 52.369,45.85 52.545,45.674 52.721,45.498 52.897,45.323 53.072,45.147 53.275,44.9 53.525,44.65 53.599,44.62 53.775,44.444 53.951,44.268 54.126,44.093 54.302,43.917 54.478,43.741 54.653,43.566 54.829,43.39 55.005,43.214 55.18,43.039 55.422,43.039 55.663,43.039 55.905,43.039 56.146,43.039 56.388,43.039 56.629,43.039 56.871,43.039 57.112,43.039 57.354,43.039 57.595,43.039 57.837,43.039 58.078,43.039 58.32,43.039 58.561,43.039 58.803,43.039 59.044,43.039 59.286,43.039 59.527,43.039 59.768,43.039 60.01,43.039 60.251,43.039 60.416,42.874 60.58,42.71 60.744,42.546 60.908,42.382 61.072,42.218 61.236,42.054 R_USB_DM.1
usb-dm-port: J_USB.7 J_USB.9 U_ESD.3 | length 7.5
  Top w0.25: J_USB.7 33.827,50.619 34.134,50.941 34.132,51.187 33.631,51.682 J_USB.9 33.029,51.65 33.209,51.65 33.389,51.65 33.775,51.9 v1(33.87,52.323) ; v1(35.519,52.954) 35.659,52.954 35.81,52.803 35.961,52.652 36.112,52.501 U_ESD.3
  Bottom w0.25: v1(33.87,52.323) 34.119,52.318 34.368,52.312 34.616,52.306 34.865,52.3 35.004,52.439 35.143,52.578 35.283,52.718 35.422,52.857 v1(35.519,52.954)
usb-dp-mcu: R_USB_DP.2 U_MAIN.31 | length 19.5
  Top w0.25: v1(59.976,51.15) 60.199,51.251 60.199,51.199 60.343,51.054 60.34,50.839 60.336,50.623 60.275,50.65 60.331,49.999 60.343,49.848 60.514,49.677 60.684,49.506 60.855,49.336 61.025,49.165 61.196,48.995 61.367,48.824 61.537,48.653 61.537,48.427 61.537,48.201 61.537,47.975 61.707,47.805 61.877,47.636 62.046,47.466 62.025,47.4 62.556,46.957 62.725,46.787 62.895,46.617 63.065,46.448 63.234,46.278 63.404,46.108 63.574,45.938 63.744,45.769 63.913,45.599 64.083,45.429 64.253,45.259 64.422,45.09 64.592,44.92 64.592,44.684 64.592,44.448 64.592,44.212 64.592,43.976 64.592,43.74 64.592,43.504 64.592,43.268 64.592,43.032 64.592,42.796 64.592,42.56 64.455,42.422 64.317,42.285 64.15,42.15 63.662,42.285 63.444,42.285 63.225,42.285 63.069,42.441 62.913,42.597 62.756,42.754 R_USB_DP.2 ; v1(60.539,55.914) 60.539,56.119 60.539,56.324 60.539,56.529 60.539,56.734 60.539,56.939 U_MAIN.31
  Bottom w0.25: v1(59.976,51.15) 60.112,51.304 60.248,51.459 60.384,51.613 60.52,51.768 60.52,52.009 60.52,52.25 60.52,52.491 60.52,52.732 60.52,52.973 60.52,53.214 60.52,53.454 60.52,53.695 60.52,53.936 60.52,54.177 60.52,54.418 60.52,54.659 60.52,54.9 60.52,55.141 60.52,55.382 60.52,55.623 60.52,55.864 60.52,55.895 v1(60.539,55.914)
usb-dp-phy: R_USB_DP.1 U_ESD.6 | length 28.4
  Top w0.25: U_ESD.6 40.418,50.45 45.452,45.416 45.544,45.416 v1(45.581,45.379) ; v1(53.556,41.669) 54.555,41.222 55.403,41.178 56.254,41.187 57.105,41.174 57.358,41.161 57.728,40.794 61.506,40.785 R_USB_DP.1
  Bottom w0.25: v1(45.581,45.379) 49.187,41.773 53.525,41.732 53.557,41.702 v1(53.556,41.669)
usb-dp-port: J_USB.8 J_USB.10 U_ESD.1 | length 8.7
  Top w0.25: J_USB.10 32.07,52.15 31.46,51.54 31.85,51.15 J_USB.8 33.551,51.15 33.574,51.173 33.582,51.155 v1(33.707,51.058) ; U_ESD.1 36.656,50.057 v1(36.656,49.618)
  Bottom w0.25: v1(33.707,51.058) 35.121,51.078 36.561,49.637 36.637,49.637 v1(36.656,49.618)
USB_CC1: J_USB.6 R_CC1.1 | length 14.6
  Top w0.15: v1(31.29,50.676) 31.816,50.15 J_USB.6 ; v1(34.019,40.213) 34.142,40.09 34.176,40.09 34.865,39.4 R_CC1.1
  Bottom w0.15: v1(31.29,50.676) 31.349,50.617 31.349,50.605 31.65,50.303 31.65,49.98 32.868,48.591 34.018,47.611 v1(34.019,40.213)
USB_CC2: J_USB.12 R_CC2.1 | length 17.3
  Top w0.15: J_USB.12 32.854,53.155 33.5,53.155 33.778,53.402 34.123,53.426 34.385,53.286 34.968,52.706 35.35,50.094 38.89,46.554 R_CC2.1
VBUS5: C_LDO_IN.1 C_VBUS.1 J_USB.3 J_USB.4 J_USB.13 J_USB.14 R_BL1.1 R_BL2.1 R_BL3.1 R_BL4.1 U_ESD.5 U_LDO.1 U_LDO.3 | length 119.3
  Top w0.3: 32.181,53.666 32.554,53.65 J_USB.14 32.849,53.8 ; J_USB.4@32.199,49.174 32.467,49.174 32.825,49.174 J_USB.4 ; J_USB.3@32.849,49 J_USB.4 ; 33.499,49.15 33.412,49.15 33.318,49.15 33.224,49.15 33.13,49.15 33.037,49.15 32.943,49.15 J_USB.4
  Top w0.312: v1(36.885,58.743) 36.899,59.166
  Top w0.325: 56.748,40.758 57.197,40.754 57.385,40.576 57.573,40.397 58.045,40.396 58.517,40.395 58.99,40.394 59.462,40.394 59.934,40.393 60.406,40.392 60.879,40.391 61.351,40.39 61.823,40.39
  Top w0.35: v1(54.952,40.772) 55.401,40.768 55.85,40.765 56.299,40.761 56.748,40.758
  Top w0.375: 33.599,49.15 34.027,49.15 v1(34.08,49.098)
  Top w0.437: 31.838,49.212 32.056,49.212 32.109,49.174 J_USB.4@32.199,49.174
  Top w0.45: 31.564,49.541 31.838,49.212 ; 31.619,53.369 31.9,53.517 32.181,53.666
  Top w0.475: J_USB.13 33.197,53.85 v1(33.544,53.749) ; 33.499,49.15 33.505,49.15 33.599,49.15 ; 36.899,59.166 36.912,59.59
  Top w0.5: 31.564,49.541 31.291,49.869 31.017,50.197 30.744,50.525 30.799,50.956 30.854,51.387 30.909,51.818 30.909,52.3 31.246,52.637 31.433,53.003 31.619,53.369 ; J_USB.3 J_USB.4@32.849,49 ; J_USB.13@32.849,53.8 J_USB.13 ; C_LDO_IN.1 35.438,60.537 U_LDO.1 ; 36.912,59.59 37.05,59.932 37.05,60.138 U_LDO.1 ; v1(37.538,49.849) 37.4,49.987 37.4,50.9 38.15,51.4 U_ESD.5 38.996,51.4 39.454,51.4 39.912,51.4 40.37,51.4 40.828,51.4 41.286,51.4 41.744,51.4 42.202,51.4 42.66,51.4 43.118,51.4 43.394,51.124 43.669,50.849 43.945,50.573 44.011,50.573 v1(44.122,50.462) ; U_LDO.3 39.35,60.517 39.233,60.4 39.233,59.733 38.9,59.4 38.733,59.4 38.567,59.233 38.233,59.233 38.067,59.4 37.9,59.4 37.567,59.733 37.567,60.4 37.4,60.567 37.421,60.567 U_LDO.1 ; 61.823,40.39 62.295,40.389 62.324,40.389 C_VBUS.1 63.078,39.99 63.255,40.168 63.74,40.168 v1(64.224,40.168) ; v1(82.21,64.931) 82.275,64.996 82.311,64.996 82.509,65.194 82.707,65.392 83.051,65.392 v1(83.395,65.392) ; v1(85.075,68.4) 85.16,68.485 85.16,68.536 85.487,68.864 85.487,69.132 R_BL1.1 85.487,69.487 86.15,70.15 86.15,70.4 86.4,70.65 88.15,70.65 89.4,69.4 R_BL2.1 89.487,69.487 90.15,70.15 90.15,70.4 90.4,70.65 92.15,70.65 93.4,69.4 R_BL3.1 93.487,69.487 94.15,70.15 94.15,70.4 94.4,70.65 96.15,70.65 97.4,69.4 R_BL4.1
  Bottom w0.325: 33.431,54.369 33.488,54.059 v1(33.544,53.749) ; 53.218,42.597 53.561,42.255 53.905,41.914 54.248,41.572 54.591,41.23 54.952,40.869 v1(54.952,40.772)
  Bottom w0.437: 33.431,54.369 33.504,54.375 33.504,54.802
  Bottom w0.5: 33.504,54.802 33.504,55.229 33.504,55.362 v1(36.885,58.743) ; v1(34.08,49.098) 36.848,49.098 37.4,49.65 37.4,49.711 v1(37.538,49.849) ; v1(44.122,50.462) 45.345,50.462 51.501,44.306 51.845,43.964 52.65,42.9 52.875,42.939 53.218,42.597 ; v1(64.224,40.168) 66.668,40.168 67.65,41.15 68.4,42.15 73.15,46.9 73.15,48.9 74.6,50.147 80.468,56.015 80.47,56.015 82.21,57.755 v1(82.21,64.931) ; v1(83.395,65.392) 85.075,67.072 v1(85.075,68.4)
VCC_3V3: C_3V3_BULK.1 C_LDO_OUT.1 C_MCU_BULK.1 C_MCU_VDD.1 C_TFT_VCI.1 C_TFT_VDDI1.1 C_TFT_VDDI2.1 C_VUSB.1 J_DEBUG.1 J_DISPLAY.7 J_DISPLAY.8 J_DISPLAY.9 J_DISPLAY.35 J_DISPLAY.40 J_DISPLAY.41 J_DISPLAY.42 R_DISPLAY_CS.2 R_DISPLAY_RESET.2 R_MCU_RESET.2 U_LDO.5 U_MAIN.29 U_MAIN.40 | length 155
  Top w0.15: J_DISPLAY.40@101.653,58.65 101.907,58.65 102.089,58.468 102.054,58.615 102.157,58.424 102.2,58.4 102.206,58.198 102.213,57.997
  Top w0.162: 102.088,56.298 102.213,56.423 102.213,56.816
  Top w0.175: 102.213,56.816 102.213,57.21 102.213,57.603 102.213,57.997
  Top w0.212: J_DISPLAY.35@101.94,56.15 102.088,56.298
  Top w0.3: 54.645,41.718 v1(54.831,41.585) ; 59.65,56.3 59.65,56.35 59.65,56.45 59.65,56.55 59.65,56.65 59.65,56.75 59.65,56.85 59.65,56.95 U_MAIN.29 59.65,57.15 59.65,57.25 59.65,57.35 59.65,57.45 59.65,57.55 59.65,57.65 59.65,57.75 59.65,57.8 59.65,57.85 ; 62.3,51.65 62.35,51.65 62.45,51.65 62.55,51.65 62.65,51.65 62.75,51.65 62.85,51.65 62.95,51.65 U_MAIN.40 ; U_MAIN.40@62.82,51.694 63.006,51.694 U_MAIN.40 ; U_MAIN.40@63.8,51.65 63.75,51.65 63.65,51.65 63.55,51.65 63.45,51.65 63.35,51.65 63.25,51.65 63.15,51.65 U_MAIN.40 ; 100.775,42.2 101.2,42.2 J_DISPLAY.7 101.4,42.3 ; J_DISPLAY.8@101.4,42.5 J_DISPLAY.8 J_DISPLAY.8@101.4,42.8 ; J_DISPLAY.9@101.4,43 J_DISPLAY.9 ; 101.4,58.8 J_DISPLAY.40 J_DISPLAY.40@101.653,58.65 ; 101.4,59 J_DISPLAY.41 J_DISPLAY.41@101.4,59.3 ; 101.4,59.5 J_DISPLAY.42 ; J_DISPLAY.35@101.94,56.15 101.67,56.15 J_DISPLAY.35 101.751,56.15 102.103,56.15
  Top w0.304: 62.3,51.696 62.463,51.695 U_MAIN.40@62.82,51.694
  Top w0.312: 102.315,55.94 v1(102.461,55.794)
  Top w0.325: 102.025,43.195 102.1,43.2 102.3,43.4 102.306,43.729 v1(102.306,44.006)
  Top w0.337: v1(55.313,40.32) 55.429,40.204 55.452,40.204
  Top w0.363: 54.322,42.612 v1(54.482,42.772)
  Top w0.375: 42.143,61.35 42.337,61.112 42.43,60.881 42.522,60.65
  Top w0.388: J_DISPLAY.9 101.75,43.175 J_DISPLAY.9@102.025,43.195
  Top w0.4: U_LDO.5 37.775,58.069 38.1,57.875 38.425,57.681 39,57.2 39.075,57.294 39.4,57.1 40,57.4 40,57.5 40.3,57.7 40.445,58.023 40.59,58.345 40.736,58.668 40.881,58.991 41.026,59.314 41.275,59.536 41.525,59.759 41.774,59.982 42.024,60.205 42.273,60.427 42.522,60.65 ; 42.143,61.35 41.954,61.7 41.764,62.05 C_LDO_OUT.1 41.81,62.639 42.045,62.877 42.281,63.116 42.516,63.354 42.751,63.593 43.9,64 44.547,63.363 44.782,63.123 45.017,62.882 45.252,62.641 C_3V3_BULK.1 ; v1(45.8,63.457) 45.8,62.712 C_3V3_BULK.1 ; v1(52.483,57.064) 51.222,57.059 C_MCU_BULK.1 49.033,55.15 48.818,54.935 48.603,54.72 48.553,54.285 48.933,54.28 49.312,54.275 48.958,54.275 48.603,54.275 48.249,54.275 48,54 46.4,54.2 46.476,54.275 46.673,54.29 46.673,54.675 46.673,55.059 46.673,55.444 46.673,55.829 46.673,56.214 46.673,56.598 46.673,56.983 46.673,57.368 46.673,57.753 46.673,58.137 46.673,58.522 46.673,58.907 46.673,59.292 46.673,59.676 46.673,60.061 46.673,60.446 46.673,60.831 46.673,61.215 46.436,61.452 46.199,61.689 45.962,61.926 45.725,62.163 C_3V3_BULK.1 ; 54.322,42.611 54.111,42.4 R_MCU_RESET.2 54.185,42.125 54.459,41.851 54.645,41.718 ; 55.452,40.204 55.695,39.961 55.938,39.718 56.181,39.475 56.551,39.475 56.92,39.475 57.29,39.475 57.66,39.475 58.03,39.475 C_VUSB.1 ; v1(57.155,58.224) 57.182,58.158 57.263,58.239 59.392,58.193 59.65,57.935 59.65,57.85 ; v1(59.155,50.876) 59.6,51.6 59.965,51.702 60.322,51.701 60.679,51.7 61.036,51.699 61.392,51.698 61.749,51.697 62.106,51.696 62.3,51.696 ; v1(59.159,52.426) 59.159,52.413 59.511,52.019 59.953,52.019 60.459,51.837 62.25,51.65 62.3,51.65 ; v1(59.169,55.682) 59.65,56.163 59.65,56.25 59.65,56.3 ; 63.8,51.65 63.85,51.65 C_MCU_VDD.1 65.712,51.472 65.534,51.294 65.494,50.969 65.5,50.6 65.7,50.4 65.721,50.411 65.987,50.177 66.254,49.943 66.521,49.709 66.788,49.475 67.054,49.241 67.321,49.007 67.7,49.007 68.079,49.007 68.459,49.007 68.838,49.007 69.217,49.007 69.596,49.007 69.975,49.007 70.354,49.008 70.734,49.008 71.113,49.008 71.492,49.008 71.871,49.008 72.25,49.008 72.629,49.008 73.009,49.008 73.388,49.008 73.767,49.009 73.989,49.009 v1(74.024,48.978) ; v1(76.487,40.81) 76.699,40.598 76.91,40.387 76.91,40.058 76.91,39.729 R_DISPLAY_CS.2 77.285,39.4 77.661,39.4 78.036,39.4 78.4,38.8 79.2,38.6 79.521,39.006 79.468,39.01 79.52,39.01 79.715,39.205 R_DISPLAY_RESET.2 C_TFT_VDDI1.1 88.145,39.655 88.4,39.91 88.6,40.2 90.024,39.91 90.38,39.91 90.635,39.655 C_TFT_VDDI2.1 91.048,39.4 91.174,39.597 91.6,40.2 92.4,40 92.689,39.873 92.678,39.72 92.496,39.733 92.869,39.733 93.242,39.733 93.408,39.567 C_TFT_VCI.1 96.325,42.15 97.605,42.219 98.2,42.55 100.6,42.2 100.775,42.2 ; 101.4,42.3 101.4,42.5 ; J_DISPLAY.8@101.4,42.8 101.4,43 ; 101.4,58.8 101.4,59 ; 101.4,59.3 101.4,59.5 ; 102.103,56.15 102.313,55.94 102.315,55.94
  Bottom w0.262: 55.173,41.233 55.352,41.056 55.352,40.703 v1@55.352,40.352
  Bottom w0.275: v1(55.313,40.32) v1@55.352,40.352
  Bottom w0.288: v1(54.831,41.585) 54.991,41.41 54.994,41.41 55.173,41.233
  Bottom w0.312: 74.022,48.581 v1(74.024,48.978)
  Bottom w0.4: v1(45.8,63.457) 45.804,63.461 45.804,63.517 48.97,66.683 J_DEBUG.1 ; v1(52.483,57.064) 52.512,57.038 52.589,57.038 53.635,58.084 v1(57.155,58.224) ; v1(54.482,42.772) 54.754,43.046 55.027,43.319 55.299,43.593 55.572,43.866 55.844,44.14 56.116,44.413 56.389,44.687 56.661,44.96 56.934,45.234 57.206,45.507 57.479,45.781 57.751,46.054 58.023,46.328 58.296,46.602 58.568,46.875 58.841,47.149 58.84,47.516 58.839,47.884 58.838,48.252 58.6,49.2 58.8,49.4 58.835,49.355 58.834,49.722 58.833,50.09 58.832,50.458 58.859,50.58 59.007,50.728 v1(59.155,50.876) ; v1(59.159,52.426) 59.104,55.601 59.156,55.652 59.156,55.669 v1(59.169,55.682) ; 74.022,48.581 74.019,48.184 74.017,47.787 74.015,47.39 74.012,46.993 74.01,46.596 74.008,46.199 74.005,45.802 74.003,45.405 74,45.008 73.998,44.611 73.996,44.214 73.993,43.816 73.991,43.419 74.265,43.146 74.538,42.872 74.812,42.598 75.086,42.325 75.36,42.051 75.633,41.777 75.907,41.503 76.181,41.23 76.455,40.956 76.455,40.842 v1(76.487,40.81) ; v1(102.306,44.006) 102.351,44.051 102.351,44.09 102.461,44.199 102.461,44.599 102.461,44.999 102.461,45.399 102.461,45.799 102.461,46.198 102.461,46.598 102.461,46.998 102.461,47.398 102.461,47.798 102.461,48.197 102.461,48.597 102.461,48.997 102.461,49.397 102.461,49.797 102.461,50.196 102.461,50.596 102.461,50.996 102.461,51.396 102.461,51.796 102.461,52.195 102.461,52.595 102.461,52.995 102.461,53.395 102.461,53.795 102.461,54.194 102.461,54.594 102.461,54.994 102.461,55.394 v1(102.461,55.794)
pads on no net: J_DISPLAY.11 J_DISPLAY.12 J_DISPLAY.13 J_DISPLAY.14 J_DISPLAY.44 J_DISPLAY.45 J_DISPLAY.46 J_DISPLAY.47 J_DISPLAY.51 J_DISPLAY.52 J_USB.5 J_USB.11 J_USB.NPTH-1 J_USB.NPTH-2 U_LDO.4 U_MAIN.1 U_MAIN.2 U_MAIN.3 U_MAIN.4 U_MAIN.5 U_MAIN.6 U_MAIN.7 U_MAIN.8 U_MAIN.9 U_MAIN.10 U_MAIN.11 U_MAIN.14 U_MAIN.15 U_MAIN.16 U_MAIN.17 U_MAIN.18 U_MAIN.19 U_MAIN.20 U_MAIN.21 U_MAIN.22 U_MAIN.23 U_MAIN.24 U_MAIN.25 U_MAIN.26 U_MAIN.27 U_MAIN.28 U_MAIN.33 U_MAIN.34 U_MAIN.35 U_MAIN.36 U_MAIN.37 U_MAIN.39 U_MAIN.43 U_MAIN.44 U_MAIN.45 U_MAIN.46 U_MAIN.47 U_MAIN.48 U_MAIN.49 U_MAIN.54 U_MAIN.55 U_MAIN.56 U_MAIN.57 U_MAIN.62 U_MAIN.63 U_MAIN.64

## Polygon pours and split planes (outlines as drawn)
GND on Bottom (solid): 107.1,77.1 25.7,77.1 25.7,25.7 107.1,25.7
GND on Bottom (solid): 57.899,59.324 57.857,59.282 57.857,54.65 57.899,54.692
GND on Bottom (solid): 60.195,52.141 59.301,51.248 59.308,51.246 59.377,51.209 59.438,51.159 59.487,51.098 59.524,51.029 59.547,50.954 59.555,50.876 59.547,50.798 59.524,50.723 59.487,50.654 59.438,50.594 59.438,50.593 59.29,50.445 59.232,50.388 59.233,50.091 59.234,49.723 59.234,49.612 60.01,50.753 59.976,50.75 59.898,50.758 59.823,50.78 59.754,50.817 59.694,50.867 59.644,50.928 59.607,50.997 59.584,51.072 59.576,51.15 59.584,51.228 59.607,51.303 59.644,51.372 59.694,51.433 59.754,51.483 59.823,51.519 59.885,51.538 60.004,51.674 60.14,51.828 60.195,51.891 60.195,52.009
GND on Bottom (solid): 60.806,47.785 60.803,47.485 60.816,47.474 60.817,47.777
GND on Bottom (solid): 57.804,50.172 56.3,48.668 56.303,48.366 56.329,48.345 56.378,48.284 56.415,48.215 56.438,48.14 56.446,48.062 56.438,47.984 56.415,47.909 56.378,47.84 56.329,47.779 56.268,47.729 56.199,47.692 56.124,47.67 56.046,47.662 55.981,47.668 55.981,47.259 56.029,47.285 56.104,47.307 56.112,47.308

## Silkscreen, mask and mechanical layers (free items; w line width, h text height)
Top Overlay:
  text "2L • BOTTOM GND POUR" at 48.4,75.4 h0.48
  text "ER-CON50HT-1 • 4-WIRE SPI" at 84.4,75.4 h0.55
  text "ER-TFT028A2-4" at 81.4,28.9 h0.58
  text "QUICK CONFIGURE • SCREEN" at 66.4,27.4 h0.72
